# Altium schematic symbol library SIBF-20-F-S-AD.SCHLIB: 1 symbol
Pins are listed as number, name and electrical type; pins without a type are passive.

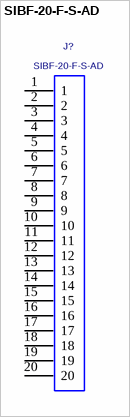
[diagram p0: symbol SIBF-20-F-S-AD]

## SIBF-20-F-S-AD
designator J?
.050" SIBF ASSEMBLY.; MANUFACTURER: SAMTEC
footprint SIBF-20-F-S-AD
pins: 1, 2, 3, 4, 5, 6, 7, 8, 9, 10, 11, 12, 13, 14, 15, 16, 17, 18, 19, 20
